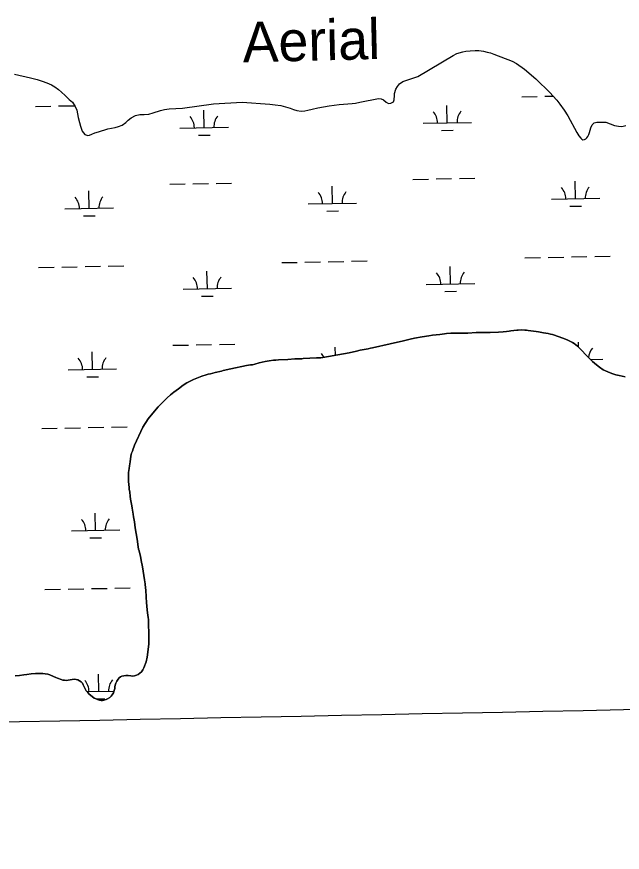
# Model space of a CAD drawing. Extents: x 3989314 to 4027622, y 243956 to 270014.
# Drawn here: x 4007202 to 4008451, y 255456 to 257182 of the extents above; entities that cross this region are included whole.
import ezdxf

# ---------------------------------------------------------------- set-up
doc = ezdxf.new("R2010")
doc.units = 0
for name, color, linetype in [('V-GRID-MAJR', 7, 'Continuous'), ('V-RIVR-EDGE', 7, 'Continuous'), ('V-RIVR-IDEN', 7, 'Continuous'), ('V-WETL-SWMP', 7, 'Continuous')]:
    doc.layers.add(name, color=color, linetype=linetype)

msp = doc.modelspace()

# ---------------------------------------------------------------- linework, layer by layer
at = {"layer": 'V-GRID-MAJR'}
msp.add_spline([(3993497.6, 255455.7), (3998815.3, 255559.8), (4004133, 255664.6), (4009450.7, 255770.2), (4014768.4, 255876.5), (4020086, 255983.7), (4025403.7, 256091.6)], degree=3, dxfattribs=at)
at = {"layer": 'V-RIVR-EDGE'}
for points in [[(4007322.5, 256996.3), (4007325.5, 256988.4), (4007328.2, 256973.3), (4007330.9, 256963.3), (4007333.2, 256955.3), (4007336.8, 256945.5), (4007342.5, 256938.6), (4007348.4, 256936.3), (4007352.1, 256937), (4007356.9, 256939.2), (4007362.8, 256941.7), (4007370.6, 256943.9), (4007389.8, 256950.1), (4007404.9, 256952.8), (4007411.6, 256954.6), (4007419.6, 256957.7), (4007426.9, 256962.9), (4007431.9, 256967.9), (4007437.5, 256972.9), (4007446.6, 256977.5), (4007455.6, 256979.3), (4007464.6, 256979.8), (4007474.1, 256980.6), (4007483.4, 256983), (4007498.5, 256988.2), (4007506.6, 256990), (4007516.4, 256991.4), (4007544.1, 256992.9), (4007607.6, 257001.8), (4007666.8, 257005.4), (4007724.2, 257000.7), (4007734.9, 256999.5), (4007746.7, 256998), (4007756, 256995.7), (4007765.8, 256992.5), (4007772.6, 256990), (4007779.4, 256987.8), (4007788.3, 256986.4), (4007796, 256987.1), (4007802.3, 256988.3), (4007811, 256990.5), (4007822.9, 256993.2), (4007846.7, 256997.5), (4007867.3, 257000.2), (4007893.5, 257002.1), (4007900.6, 257003), (4007909.6, 257005.2), (4007948, 257013), (4007953.8, 257011.7), (4007958.5, 257009.8), (4007964, 257005.3), (4007969.1, 257002.2), (4007973.5, 257002.7), (4007979.3, 257005.6), (4007980.6, 257009.8), (4007981.4, 257018.6), (4007981.5, 257023), (4007984, 257031.8), (4007987.2, 257037.8), (4007991.5, 257042.8), (4007998.3, 257047.6), (4008006.5, 257050.8), (4008029.1, 257058.4), (4008101.9, 257101.8), (4008109.6, 257105.3), (4008121.9, 257109.2), (4008128.1, 257110.5), (4008137.6, 257111.4), (4008147.4, 257111.9), (4008155.3, 257111.9), (4008164.9, 257110.5), (4008172.5, 257108.6), (4008179, 257106.8), (4008186, 257104.5), (4008223.7, 257090), (4008233, 257085.3), (4008249.2, 257073.4), (4008272.6, 257053.1), (4008302.7, 257024.5), (4008308, 257018.5), (4008315.9, 257009.1), (4008322.5, 257000.8), (4008331, 256988.8), (4008338.8, 256976.6), (4008357.1, 256942.4), (4008361.4, 256935.8), (4008365.4, 256931)], [(4007197.3, 257063.1), (4007230.3, 257055.2), (4007243.9, 257051.7), (4007254, 257048.6), (4007264, 257045), (4007273.5, 257040.7), (4007280.6, 257036.7), (4007287.9, 257031.3), (4007294.3, 257025.8), (4007301.8, 257019.1), (4007310.1, 257010.9), (4007316.6, 257004.9), (4007322.5, 256996.3)], [(4008365.4, 256931), (4008368, 256928.4), (4008369.9, 256927.5), (4008373.2, 256927.8), (4008376, 256929.2), (4008378.3, 256931.5), (4008380, 256934.1), (4008382.1, 256938.5), (4008383.4, 256942.5), (4008384.6, 256947.2), (4008386, 256951.8), (4008389.1, 256958), (4008393.2, 256962.3), (4008398.9, 256964.1), (4008417.2, 256963.5), (4008435.3, 256957.2), (4008443.7, 256955.4), (4008450, 256955), (4008458.2, 256956.8)], [(4007688.5, 256462.8), (4007692.9, 256464.2), (4007702.2, 256466.8), (4007714, 256469.5), (4007718.2, 256469.9), (4007722.9, 256470.8), (4007731.6, 256472.1), (4007736.4, 256472.4), (4007741.7, 256473.1), (4007761.4, 256473.7), (4007775.8, 256474.9), (4007778.9, 256474.9), (4007782, 256475.1), (4007789.7, 256475.1), (4007792.7, 256475.5), (4007820.3, 256477.2), (4007825.6, 256477.3), (4007829.3, 256477), (4007833.6, 256477.6), (4007887.7, 256487.6), (4007903, 256490.7), (4007910.4, 256492.6), (4007926.6, 256495.9), (4007932, 256497.2), (4007936.1, 256497.9), (4007972.2, 256505.8), (4007987.6, 256509.4), (4007996.8, 256511.7), (4008013.7, 256515.3), (4008022.7, 256517.5), (4008038.5, 256520.4), (4008051.9, 256522.3), (4008059.6, 256523.7), (4008074.8, 256525.5), (4008084.2, 256526.4), (4008088.4, 256527.1), (4008097.7, 256528), (4008104.1, 256528.1), (4008114.1, 256527.7), (4008124.8, 256527.7), (4008132.2, 256527.9), (4008149.8, 256529), (4008154.4, 256529), (4008161, 256529.2), (4008178.4, 256529.2), (4008196, 256530.2), (4008205.5, 256530.6), (4008212.3, 256531.4), (4008217.6, 256532.3), (4008220.9, 256532.5), (4008233.3, 256534), (4008236.5, 256534.1), (4008243.9, 256534.7), (4008250.4, 256534.1), (4008253.6, 256534.1), (4008256.7, 256533.8), (4008273.8, 256531.3), (4008278.2, 256530.4), (4008288.6, 256528.9), (4008298, 256527.2), (4008303.3, 256525.9), (4008307.3, 256524.9), (4008321.3, 256520.7), (4008333.9, 256515.9), (4008338.8, 256513.8), (4008345.8, 256510.2), (4008348.6, 256508.6), (4008352, 256506.4), (4008358.7, 256500.9), (4008369.3, 256490.8), (4008374.9, 256484.8), (4008379.4, 256479.6), (4008382.8, 256476.1), (4008389.7, 256469.4), (4008398.1, 256462.4), (4008404.5, 256457.5), (4008411.9, 256452.4), (4008416.4, 256450.2), (4008426.2, 256446.2), (4008431.5, 256444.3), (4008438.1, 256442.2), (4008444.7, 256440.5), (4008457, 256437.9)], [(4007404.2, 255797.3), (4007405, 255801), (4007406, 255804.7), (4007408.5, 255809.4), (4007411, 255813.4), (4007413, 255816), (4007415.5, 255818), (4007418.4, 255819.6), (4007422.5, 255820.5), (4007427, 255820.9), (4007431.6, 255820.8), (4007437.1, 255820), (4007440.6, 255819.7), (4007445, 255820.2), (4007448.6, 255821.4), (4007452.1, 255823.1), (4007455.9, 255825.4), (4007459.1, 255828.5), (4007462.1, 255832.5), (4007464.2, 255836.8), (4007468.7, 255849.1), (4007470.9, 255858.4), (4007471.8, 255863.6), (4007474, 255886), (4007474.1, 255914.9), (4007473.7, 255919.1), (4007473.6, 255923.2), (4007473.7, 255927.9), (4007473.4, 255935.6), (4007472.8, 255941.1), (4007472.5, 255945), (4007470.9, 255956.7), (4007470.1, 255964.3), (4007469.4, 255971.8), (4007468.9, 255983), (4007467.8, 255997.8), (4007467.7, 256001.4), (4007466.8, 256009.9), (4007465.6, 256018.4), (4007462.4, 256036.7), (4007461.2, 256045), (4007458.8, 256058.4), (4007457.6, 256062.9), (4007456.1, 256070.4), (4007454.9, 256074.7), (4007454.1, 256078.3), (4007453.1, 256081.8), (4007452.2, 256086.4), (4007450.1, 256102.5), (4007446.3, 256126), (4007444.6, 256138), (4007442.8, 256148.6), (4007442, 256154.3), (4007441.2, 256157.9), (4007439.9, 256166.7), (4007438.9, 256171.2), (4007436.7, 256185.1), (4007436.1, 256191.5), (4007434.8, 256199.3), (4007433.9, 256205.9), (4007433.6, 256209.3), (4007432.2, 256221.4), (4007432.1, 256231.4), (4007432.6, 256240.1), (4007433.5, 256248.6), (4007434.6, 256254.2), (4007435.6, 256262.2), (4007437.3, 256274.1), (4007437.6, 256277.2), (4007438.2, 256280.2), (4007440.3, 256284.2), (4007442.2, 256289), (4007443.4, 256292.6), (4007445, 256296.6), (4007448.8, 256305.9), (4007457.7, 256325.1), (4007462.2, 256333.6), (4007472.9, 256350.7), (4007478.8, 256358.3), (4007493.5, 256375.9), (4007505.1, 256387.7), (4007508.8, 256391.1), (4007511.9, 256394.2), (4007519.1, 256400.6), (4007526.1, 256406.3), (4007535.2, 256412.9), (4007545.3, 256420.5), (4007552.5, 256425.1), (4007556.5, 256427.5), (4007566.2, 256432.6), (4007583.4, 256439), (4007592.3, 256441.9), (4007596.5, 256443), (4007601.8, 256444.2), (4007611, 256446.6), (4007623.9, 256449.6), (4007627.4, 256450.6), (4007643.3, 256454.3), (4007676, 256461), (4007684.1, 256462.3), (4007688.5, 256462.8)], [(4007198.2, 255820.5), (4007207.5, 255820.8), (4007216.2, 255822.3), (4007222.9, 255823.2), (4007231.3, 255824.1), (4007240.5, 255824.9), (4007246.1, 255824.9), (4007255.7, 255825.3), (4007260.7, 255824.5), (4007265.9, 255823.5), (4007269.8, 255822.2), (4007277.9, 255818.5), (4007282.3, 255817), (4007285.6, 255815.4), (4007293.2, 255812.6), (4007296.9, 255811.5), (4007300.2, 255811), (4007304.3, 255810.7), (4007307.8, 255811.1), (4007316.1, 255812.7), (4007320.1, 255813.1), (4007324.3, 255812.5), (4007327.7, 255811.6), (4007331.5, 255810.2), (4007334.5, 255807.9), (4007337.3, 255805.2), (4007338.6, 255801.9), (4007345.3, 255789.4), (4007348.1, 255785.7), (4007351.2, 255782.2), (4007357.1, 255777.2), (4007361.6, 255774.2), (4007365.6, 255772.4), (4007368.6, 255771.2), (4007372.8, 255769.9), (4007375.7, 255769.4), (4007378.8, 255769.5), (4007386.1, 255771.5), (4007389.3, 255772.8), (4007393.5, 255775.2), (4007396.8, 255778.3), (4007398.8, 255780.9), (4007401.2, 255785.1), (4007402.9, 255789.8), (4007403.8, 255794.1), (4007404.2, 255797.3)]]:
    msp.add_lwpolyline(points, dxfattribs=at)
at = {"layer": 'V-WETL-SWMP'}
for p, q in [((4008243.7, 257016.2), (4008275.7, 257016.8)), ((4008291.7, 257017.2), (4008308.9, 257017.5)), ((4007240.1, 256996.2), (4007272.1, 256996.8)), ((4007288.1, 256997.2), (4007320.1, 256997.8)), ((4007588.4, 256952.4), (4007587.6, 256988.4)), ((4008090.2, 256962.4), (4008089.5, 256998.4)), ((4007538.4, 256951.4), (4007638.4, 256953.4)), ((4008040.2, 256961.4), (4008140.2, 256963.4)), ((4007576.7, 256936.7), (4007600.7, 256937.2)), ((4008078.5, 256946.7), (4008102.5, 256947.2)), ((4008115.1, 256847.4), (4008147, 256848.1)), ((4007517.3, 256835.5), (4007549.3, 256836.1)), ((4007565.3, 256836.5), (4007597.3, 256837.1)), ((4007613.2, 256837.4), (4007645.2, 256838.1)), ((4007853, 256795.8), (4007852.3, 256831.8)), ((4008019.1, 256845.5), (4008051.1, 256846.1)), ((4008067.1, 256846.5), (4008099.1, 256847.1)), ((4008354.8, 256805.8), (4008354.1, 256841.8)), ((4007351.2, 256785.8), (4007350.4, 256821.8)), ((4007803, 256794.8), (4007903, 256796.8)), ((4008304.8, 256804.8), (4008404.8, 256806.8)), ((4007301.2, 256784.8), (4007401.2, 256786.8)), ((4007841.3, 256780.1), (4007865.3, 256780.6)), ((4008343.1, 256790.1), (4008367.1, 256790.6)), ((4007339.5, 256770.1), (4007363.5, 256770.6)), ((4007796.5, 256674.5), (4007828.5, 256675.2)), ((4007844.5, 256675.5), (4007876.5, 256676.1)), ((4007892.5, 256676.5), (4007924.5, 256677.1)), ((4008250.3, 256683.6), (4008282.3, 256684.2)), ((4008298.3, 256684.5), (4008330.3, 256685.2)), ((4008346.3, 256685.5), (4008378.3, 256686.1)), ((4008394.3, 256686.5), (4008426.3, 256687.1)), ((4007246.7, 256663.6), (4007278.7, 256664.2)), ((4007294.7, 256664.5), (4007326.7, 256665.2)), ((4007342.7, 256665.5), (4007374.7, 256666.1)), ((4007390.7, 256666.5), (4007422.7, 256667.1)), ((4007748.5, 256673.6), (4007780.5, 256674.2)), ((4008096.8, 256629.8), (4008096.1, 256665.8)), ((4007595, 256619.8), (4007594.3, 256655.8)), ((4008046.8, 256628.8), (4008146.8, 256630.8)), ((4007545, 256618.8), (4007645, 256620.8)), ((4008085.1, 256614.1), (4008109.1, 256614.6)), ((4007583.3, 256604.1), (4007607.3, 256604.6)), ((4007523.9, 256502.9), (4007555.9, 256503.5)), ((4007571.9, 256503.9), (4007603.9, 256504.5)), ((4007619.9, 256504.8), (4007651.9, 256505.5)), ((4008360.9, 256498.8), (4008360.7, 256509.1)), ((4007357.8, 256453.2), (4007357.1, 256489.1)), ((4007859.2, 256482.3), (4007858.9, 256499.1)), ((4008385.3, 256473.6), (4008411.4, 256474.2)), ((4007307.8, 256452.2), (4007407.8, 256454.1)), ((4007346.1, 256437.5), (4007370.1, 256438)), ((4007253.4, 256331), (4007285.4, 256331.6)), ((4007301.3, 256331.9), (4007333.3, 256332.6)), ((4007349.3, 256332.9), (4007381.3, 256333.5)), ((4007397.3, 256333.8), (4007429.3, 256334.5)), ((4007364.4, 256120.5), (4007363.7, 256156.5)), ((4007314.4, 256119.5), (4007414.4, 256121.5)), ((4007352.7, 256104.9), (4007376.7, 256105.4)), ((4007404, 256001.2), (4007436, 256001.9)), ((4007260, 255998.4), (4007292, 255999)), ((4007308, 255999.3), (4007340, 256000)), ((4007356, 256000.3), (4007388, 256000.9)), ((4007371, 255787.9), (4007370.3, 255823.9)), ((4007346.8, 255787.5), (4007402.5, 255788.6)), ((4007365.6, 255772.4), (4007383.4, 255772.7))]:
    msp.add_line(p, q, dxfattribs=at)
for points in [[(4007746.7, 256998), (4007756, 256995.7), (4007765.8, 256992.5), (4007772.6, 256990), (4007779.4, 256987.8), (4007788.3, 256986.4), (4007796, 256987.1), (4007802.3, 256988.3), (4007811, 256990.5), (4007822.9, 256993.2), (4007846.7, 256997.5), (4007867.3, 257000.2), (4007893.5, 257002.1), (4007900.6, 257003), (4007909.6, 257005.2), (4007948, 257012.9), (4007953.8, 257011.7), (4007958.5, 257009.8), (4007964, 257005.3), (4007969.1, 257002.2), (4007973.5, 257002.7), (4007979.3, 257005.6), (4007980.6, 257009.8), (4007981.4, 257018.6), (4007981.5, 257023), (4007984, 257031.8), (4007987.2, 257037.8), (4007991.5, 257042.8), (4007998.3, 257047.6), (4008006.5, 257050.8), (4008029.1, 257058.4), (4008101.9, 257101.8), (4008109.6, 257105.3), (4008121.9, 257109.2), (4008128.1, 257110.5), (4008137.6, 257111.4), (4008147.4, 257111.9), (4008155.3, 257111.9), (4008164.9, 257110.5), (4008172.5, 257108.6), (4008179, 257106.8), (4008186, 257104.5), (4008223.7, 257090), (4008233, 257085.3), (4008249.2, 257073.4), (4008272.6, 257053.1), (4008302.7, 257024.5), (4008308, 257018.5), (4008315.9, 257009.1), (4008322.5, 257000.8), (4008331, 256988.8), (4008338.8, 256976.6), (4008357.1, 256942.4), (4008361.4, 256935.8), (4008365.4, 256931), (4008368, 256928.4), (4008369.9, 256927.5), (4008373.2, 256927.8), (4008376, 256929.2), (4008378.3, 256931.5), (4008380, 256934.1), (4008382.1, 256938.5), (4008383.4, 256942.5), (4008384.6, 256947.2), (4008386, 256951.8), (4008389.1, 256958.1), (4008393.2, 256962.3), (4008398.9, 256964.1), (4008417.2, 256963.5), (4008435.3, 256957.2), (4008443.7, 256955.4), (4008450, 256955), (4008458.2, 256956.8)], [(4007197.3, 257063.1), (4007230.3, 257055.2), (4007243.9, 257051.7), (4007254, 257048.6), (4007264, 257045), (4007273.5, 257040.7), (4007280.6, 257036.7), (4007287.9, 257031.3), (4007294.3, 257025.8), (4007301.8, 257019.1), (4007310.1, 257010.9), (4007316.6, 257004.9), (4007322.5, 256996.3), (4007325.5, 256988.4), (4007328.2, 256973.3), (4007330.9, 256963.3), (4007333.2, 256955.3), (4007336.8, 256945.5), (4007342.5, 256938.6), (4007348.4, 256936.3), (4007352.1, 256937), (4007356.9, 256939.2), (4007362.8, 256941.7), (4007370.6, 256943.9), (4007389.8, 256950.1), (4007404.9, 256952.8), (4007411.6, 256954.6), (4007419.6, 256957.7), (4007426.9, 256962.9), (4007431.9, 256967.9), (4007437.5, 256972.9), (4007446.6, 256977.5), (4007455.6, 256979.3), (4007464.6, 256979.8), (4007474.1, 256980.6), (4007483.4, 256983), (4007498.5, 256988.2), (4007506.6, 256990), (4007516.4, 256991.4), (4007544.1, 256992.9), (4007607.6, 257001.8), (4007666.8, 257005.4), (4007724.2, 257000.7), (4007734.9, 256999.5), (4007746.7, 256998)], [(4008217.6, 256532.3), (4008212.3, 256531.4), (4008205.5, 256530.6), (4008196, 256530.2), (4008178.4, 256529.2), (4008161, 256529.2), (4008154.4, 256529), (4008149.8, 256529), (4008132.2, 256527.9), (4008124.8, 256527.7), (4008114.1, 256527.7), (4008104.1, 256528.1), (4008097.7, 256528), (4008088.4, 256527.1), (4008084.2, 256526.4), (4008074.8, 256525.5), (4008059.6, 256523.7), (4008051.9, 256522.3), (4008038.5, 256520.4), (4008022.7, 256517.5), (4008013.7, 256515.3), (4007996.8, 256511.7), (4007987.6, 256509.4), (4007972.2, 256505.8), (4007936.1, 256497.9), (4007932, 256497.2), (4007926.6, 256495.9), (4007910.4, 256492.6), (4007903, 256490.7), (4007887.7, 256487.6), (4007833.6, 256477.6), (4007829.3, 256477), (4007825.6, 256477.3), (4007820.3, 256477.2), (4007792.7, 256475.5), (4007789.7, 256475.1), (4007782, 256475.1), (4007778.9, 256474.9), (4007775.8, 256474.9), (4007761.4, 256473.7), (4007741.7, 256473.1), (4007736.4, 256472.4), (4007731.6, 256472.1), (4007722.9, 256470.8), (4007718.2, 256469.9), (4007714, 256469.5), (4007702.2, 256466.8), (4007692.9, 256464.2), (4007688.5, 256462.8), (4007684.1, 256462.3), (4007676, 256461), (4007643.3, 256454.3), (4007627.4, 256450.6), (4007623.9, 256449.6), (4007611, 256446.6), (4007601.8, 256444.2), (4007596.5, 256443), (4007592.3, 256441.9), (4007583.4, 256439), (4007566.2, 256432.6), (4007556.5, 256427.5), (4007552.5, 256425.1), (4007545.3, 256420.5), (4007535.2, 256412.9), (4007526.1, 256406.3), (4007519.1, 256400.6), (4007511.9, 256394.2), (4007508.8, 256391.1), (4007505.1, 256387.7), (4007493.5, 256375.9), (4007478.8, 256358.3), (4007472.9, 256350.7), (4007462.2, 256333.6), (4007457.7, 256325.1), (4007448.8, 256305.9), (4007445, 256296.6), (4007443.4, 256292.6), (4007442.2, 256289), (4007440.3, 256284.2), (4007438.2, 256280.2), (4007437.6, 256277.2), (4007437.3, 256274.1), (4007435.6, 256262.2), (4007434.6, 256254.2), (4007433.5, 256248.6), (4007432.6, 256240.1), (4007432.1, 256231.4), (4007432.2, 256221.4), (4007433.6, 256209.3), (4007433.9, 256205.9), (4007434.8, 256199.3), (4007436.1, 256191.5), (4007436.7, 256185.1), (4007438.9, 256171.2), (4007439.9, 256166.7), (4007441.2, 256157.9), (4007442, 256154.3), (4007442.8, 256148.6), (4007444.6, 256138), (4007446.3, 256126.1), (4007450.1, 256102.5)], [(4008457, 256437.9), (4008444.7, 256440.5), (4008438.1, 256442.2), (4008431.5, 256444.3), (4008426.2, 256446.2), (4008416.4, 256450.2), (4008411.9, 256452.4), (4008404.5, 256457.5), (4008398.1, 256462.4), (4008389.7, 256469.4), (4008382.8, 256476.1), (4008379.4, 256479.6), (4008374.9, 256484.8), (4008369.3, 256490.8), (4008358.7, 256500.9), (4008352, 256506.4), (4008348.6, 256508.6), (4008345.8, 256510.2), (4008338.8, 256513.8), (4008333.9, 256515.9), (4008321.3, 256520.7), (4008307.3, 256524.9), (4008303.3, 256525.9), (4008298, 256527.2), (4008288.6, 256528.9), (4008278.2, 256530.4), (4008273.8, 256531.3), (4008256.7, 256533.8), (4008253.6, 256534.1), (4008250.4, 256534.1), (4008243.9, 256534.7), (4008236.5, 256534.1), (4008233.3, 256534), (4008220.9, 256532.5), (4008217.6, 256532.3)], [(4007450.1, 256102.5), (4007452.2, 256086.4), (4007453.1, 256081.8), (4007454.1, 256078.3), (4007454.9, 256074.7), (4007456.1, 256070.4), (4007457.6, 256062.9), (4007458.8, 256058.4), (4007461.2, 256045), (4007462.4, 256036.7), (4007465.6, 256018.4), (4007466.8, 256009.9), (4007467.7, 256001.4), (4007467.8, 255997.8), (4007468.9, 255983), (4007469.4, 255971.8), (4007470.1, 255964.3), (4007470.9, 255956.7), (4007472.5, 255945), (4007472.8, 255941.1), (4007473.4, 255935.6), (4007473.7, 255927.9), (4007473.6, 255923.2), (4007473.7, 255919.1), (4007474.1, 255914.9), (4007474, 255886), (4007471.8, 255863.6), (4007470.9, 255858.4), (4007468.7, 255849.1), (4007464.2, 255836.8), (4007462.1, 255832.5), (4007459.1, 255828.5), (4007455.9, 255825.4), (4007452.1, 255823.1), (4007448.6, 255821.4), (4007445, 255820.2), (4007440.6, 255819.7), (4007437.1, 255820), (4007431.6, 255820.8), (4007427, 255820.9), (4007422.5, 255820.5), (4007418.4, 255819.6), (4007415.5, 255818), (4007413, 255816), (4007411, 255813.4), (4007408.5, 255809.4), (4007406, 255804.7), (4007405, 255801), (4007404.2, 255797.3), (4007403.8, 255794.1), (4007402.9, 255789.8), (4007401.2, 255785.1), (4007398.8, 255780.9), (4007396.8, 255778.3), (4007393.5, 255775.2), (4007389.3, 255772.8), (4007386.1, 255771.5), (4007378.8, 255769.5), (4007375.7, 255769.4), (4007372.8, 255769.9), (4007368.6, 255771.2), (4007365.6, 255772.4), (4007361.6, 255774.2), (4007357.1, 255777.2), (4007351.2, 255782.2), (4007348.1, 255785.7), (4007345.3, 255789.4), (4007338.6, 255801.9), (4007337.3, 255805.2), (4007334.5, 255807.9), (4007331.5, 255810.2), (4007327.7, 255811.6), (4007324.3, 255812.5), (4007320.1, 255813.1), (4007316.1, 255812.7), (4007307.8, 255811.1), (4007304.3, 255810.7), (4007300.2, 255811), (4007296.9, 255811.5), (4007293.2, 255812.6), (4007285.6, 255815.4), (4007282.3, 255817), (4007277.9, 255818.5), (4007269.8, 255822.2), (4007265.9, 255823.5), (4007260.7, 255824.5), (4007255.7, 255825.3), (4007246.1, 255824.9), (4007240.5, 255824.9), (4007231.3, 255824.1), (4007222.9, 255823.2), (4007216.2, 255822.3), (4007207.5, 255820.8), (4007198.2, 255820.5)]]:
    msp.add_lwpolyline(points, dxfattribs=at)
for centre, start, end in [((4008145.4, 256964), 140.3699, 181.9135), ((4007533.1, 256951.8), 0.3699, 41.9135), ((4007643.6, 256954), 140.3699, 181.9135), ((4008034.9, 256961.8), 0.3699, 41.9135), ((4007797.7, 256795.1), 0.3699, 41.9135), ((4007908.2, 256797.3), 140.3699, 181.9135), ((4008299.5, 256805.1), 0.3699, 41.9135), ((4008410, 256807.3), 140.3699, 181.9135), ((4007295.9, 256785.1), 0.3699, 41.9135), ((4007406.4, 256787.3), 140.3699, 181.9135), ((4007539.7, 256619.1), 0.3699, 41.9135), ((4007650.2, 256621.3), 140.3699, 181.9135), ((4008041.6, 256629.1), 0.3699, 41.9135), ((4008152, 256631.4), 140.3699, 181.9135), ((4007804.4, 256462.5), 26.0418, 41.9135), ((4008416.6, 256474.7), 140.3699, 175.5728), ((4007302.5, 256452.5), 0.3699, 41.9135), ((4007413, 256454.7), 140.3699, 181.9135), ((4007309.2, 256119.9), 0.3699, 41.9135), ((4007419.6, 256122.1), 140.3699, 181.9135), ((4007426.3, 255789.5), 140.3699, 181.9135), ((4007315.8, 255787.3), 0.3699, 41.9135)]:
    msp.add_arc(centre, 35.2, start, end, dxfattribs=at)

# ---------------------------------------------------------------- texts
at = {"layer": 'V-RIVR-IDEN'}
msp.add_text('Aerial', height=83, rotation=1.424, dxfattribs=at).set_placement((4007668.6, 257087.3))

doc.saveas('drawing.dxf')
